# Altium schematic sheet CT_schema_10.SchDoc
size 391 x 385 mm
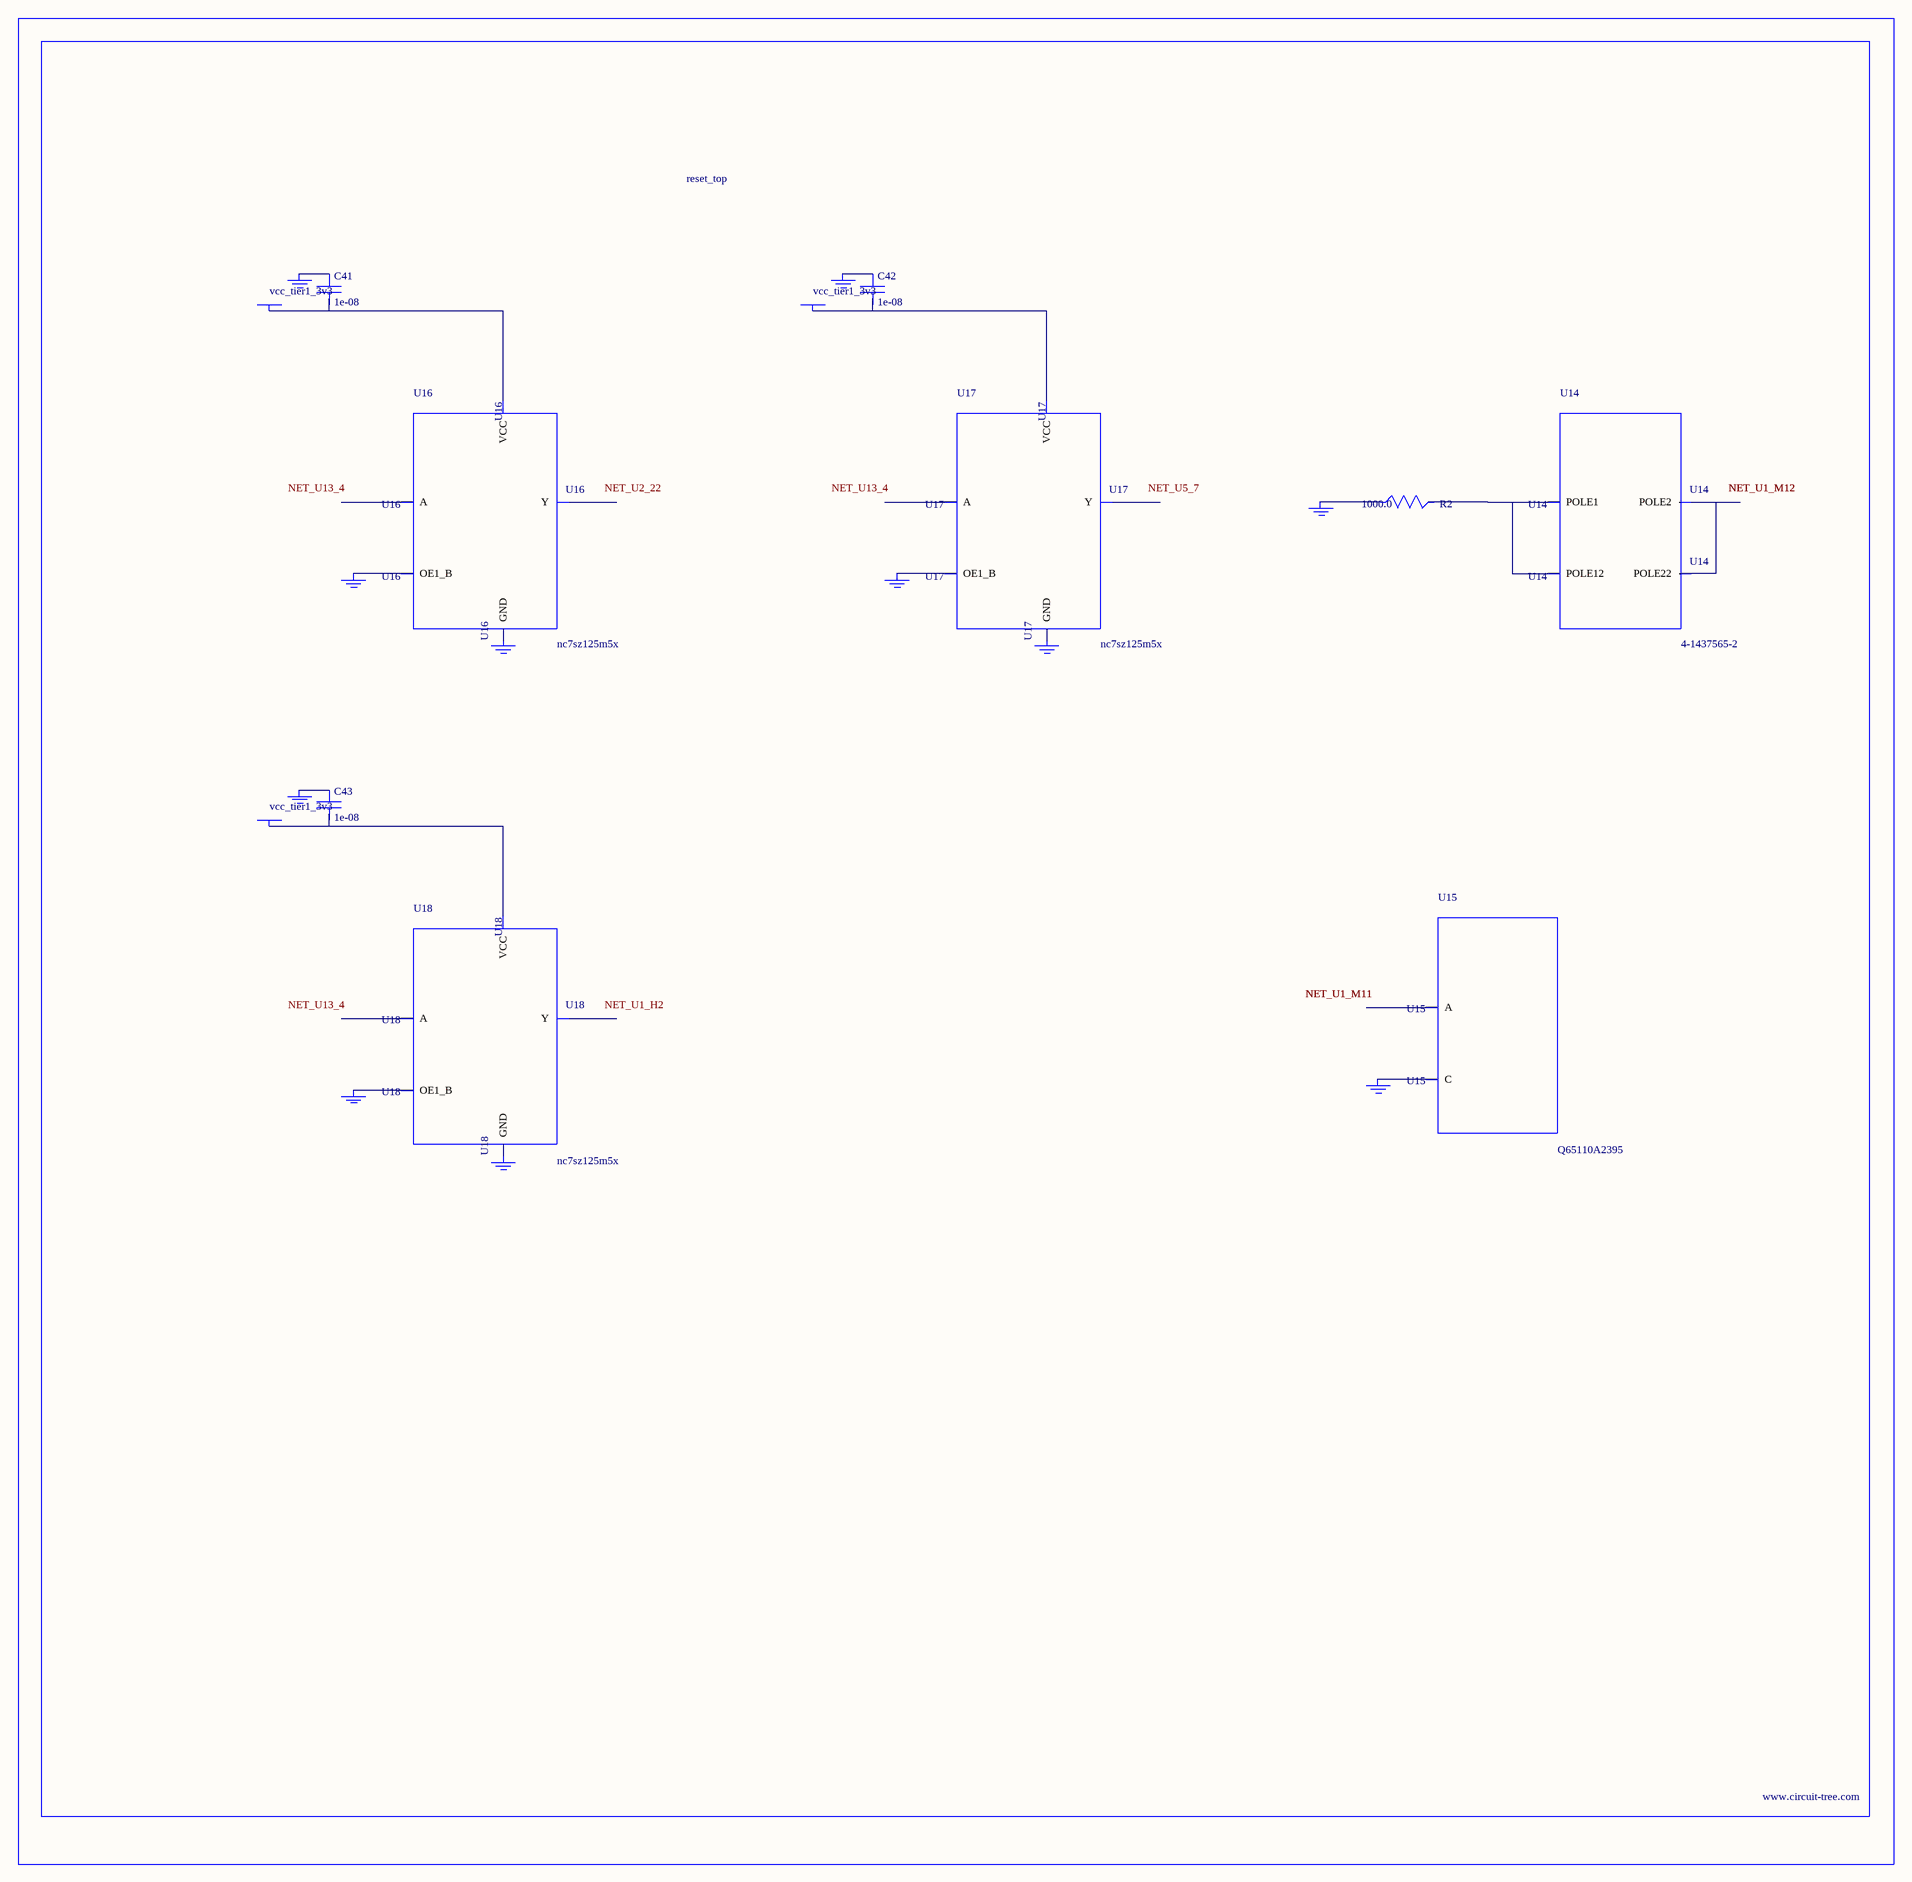
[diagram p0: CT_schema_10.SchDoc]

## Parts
BORDER9  (no value)
C41  1e-08  [C0402]
C42  1e-08  [C0402]
C43  1e-08  [C0402]
GND_INSTANCE_9_0  (no value)
GND_INSTANCE_9_1  (no value)
GND_INSTANCE_9_2  (no value)
GND_INSTANCE_9_3  (no value)
GND_INSTANCE_9_4  (no value)
GND_INSTANCE_9_5  (no value)
GND_INSTANCE_9_6  (no value)
GND_INSTANCE_9_7  (no value)
GND_INSTANCE_9_8  (no value)
GND_INSTANCE_9_9  (no value)
GND_INSTANCE_9_10  (no value)
POWER_INSTANCE_9_0  vcc_tier1_3v3
POWER_INSTANCE_9_1  vcc_tier1_3v3
POWER_INSTANCE_9_2  vcc_tier1_3v3
R2  1000.0  [R0603]
U14  4-1437565-2  [SW_4-1437565-2]
U15  Q65110A2395  [LGM67K-G1J2-24-Z]
U16  nc7sz125m5x  [NC7SZ125M5X]
U17  nc7sz125m5x  [NC7SZ125M5X]
U18  nc7sz125m5x  [NC7SZ125M5X]

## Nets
NetC41_1: C41.1 GND_INSTANCE_9_2.0(GND)
NetC41_2: C41.2 POWER_INSTANCE_9_0.0(PWR) U16.5(VCC)
NetC42_1: C42.1 GND_INSTANCE_9_5.0(GND)
NetC42_2: C42.2 POWER_INSTANCE_9_1.0(PWR) U17.5(VCC)
NetC43_1: C43.1 GND_INSTANCE_9_8.0(GND)
NetC43_2: C43.2 POWER_INSTANCE_9_2.0(PWR) U18.5(VCC)
NetGND_INSTANCE_9_0_0: GND_INSTANCE_9_0.0(GND) R2.1
NetGND_INSTANCE_9_1_0: GND_INSTANCE_9_1.0(GND) U15.C
NetGND_INSTANCE_9_3_0: GND_INSTANCE_9_3.0(GND) U16.1(OE1_B)
NetGND_INSTANCE_9_4_0: GND_INSTANCE_9_4.0(GND) U16.3(GND)
NetGND_INSTANCE_9_6_0: GND_INSTANCE_9_6.0(GND) U17.1(OE1_B)
NetGND_INSTANCE_9_7_0: GND_INSTANCE_9_7.0(GND) U17.3(GND)
NetGND_INSTANCE_9_9_0: GND_INSTANCE_9_9.0(GND) U18.1(OE1_B)
NetGND_INSTANCE_9_10_0: GND_INSTANCE_9_10.0(GND) U18.3(GND)
NetR2_2: R2.2 U14.1(POLE1) U14.2(POLE12)
NetU14_3: U14.3(POLE2) U14.4(POLE22)

Not connected (* = marked no-connect by the designer): U15 A; U16 2(A) 4(Y); U17 2(A) 4(Y); U18 2(A) 4(Y)

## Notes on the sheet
- Labels drawn without touching a wire or pin: NET_U1_H2, NET_U2_22, NET_U5_7, NET_U13_4

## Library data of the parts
BORDER9 = BORDER_PAGE9
C41-C43 = C0402C103K3RAC
GND_INSTANCE_9_0-GND_INSTANCE_9_10 = GND
POWER_INSTANCE_9_0-POWER_INSTANCE_9_2 = PWR
R2 = RC0603JR-071KL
